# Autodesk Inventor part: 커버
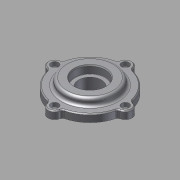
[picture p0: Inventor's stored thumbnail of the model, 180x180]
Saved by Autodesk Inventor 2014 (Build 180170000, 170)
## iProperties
Company: 한국ATC센터
Created: 2015-12
Part Number: 커버
Document SubType Name: Modeling
Designer: mdu
Density: 1 g/cm^3
Material: 일반
Mass: 49.9043 g
Surface Area: 145.431 cm^2
Volume: 49.9043 cm^3
Appearance: Default
Author: mdu
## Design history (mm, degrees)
sketch "스케치1"
  geometry: C1 r 1.621 at (0, 6.75) reference; C2 r 1.621 at (-37, -30.25) reference; C3 r 1.621 at (0, -67.25) reference; C4 r 1.621 at (37, -30.25) reference; C5 r 10 at (0, -30.25) reference; C6 r 12 at (0, -30.25); C7 r 24.5 at (0, -30.25) reference; A1 r 3 centre (-38.77, -20.408) between (-38.239, -23.361) and (-35.862, -21.146) reference; A2 r 7 centre (-37, -30.25) between (-38.239, -23.361) and (-38.239, -37.139) reference; A3 r 3 centre (-38.77, -40.092) between (-35.862, -39.354) and (-38.239, -37.139) reference; A4 r 37 centre (0, -30.25) between (-35.862, -39.354) and (-9.104, -66.113) reference; A5 r 3 centre (-9.842, -69.02) between (-6.889, -68.489) and (-9.104, -66.113) reference; A6 r 7 centre (0, -67.25) between (-6.889, -68.489) and (6.889, -68.489) reference; A7 r 3 centre (9.842, -69.02) between (9.104, -66.112) and (6.889, -68.489) reference; A8 r 37 centre (0, -30.25) between (9.104, -66.112) and (35.863, -39.354) reference; A9 r 3 centre (38.77, -40.092) between (38.239, -37.139) and (35.863, -39.354) reference; A10 r 7 centre (37, -30.25) between (38.239, -37.139) and (38.239, -23.361) reference; A11 r 3 centre (38.77, -20.408) between (35.863, -21.146) and (38.239, -23.361) reference; A12 r 37 centre (0, -30.25) between (35.863, -21.146) and (9.104, 5.612) reference; A13 r 3 centre (9.842, 8.52) between (6.889, 7.989) and (9.104, 5.612) reference; A14 r 7 centre (0, 6.75) between (6.889, 7.989) and (-6.889, 7.989) reference; A15 r 3 centre (-9.842, 8.52) between (-9.104, 5.612) and (-6.889, 7.989) reference; A16 r 37 centre (0, -30.25) between (-9.104, 5.612) and (-35.862, -21.146) reference; 1 further point
  constraints: 1 centre point, 1 coincident
  dimensions: "d2" = 2 radial gap between concentric circles of C6 C5
extrude "돌출1" new body sketch "스케치1" distance "d0" = 8; taper "d1" = 0 deg
sketch "스케치2"
  geometry: C1 r 23.5 at (0, -30.25) reference; C2 r 12 at (0, -30.25) reference; 1 further point
extrude "돌출2" join sketch "스케치2" distance "d4" = 5; taper "d5" = 0 deg
sketch "스케치3"
  geometry: C1 r 23.5 at (0, 0) reference; C2 r 20.5 at (0, 0); 1 further point
  constraints: 1 centre point
  dimensions: "d6" = 3 radial gap between concentric circles of C2 C1
node "작업 평면1"
extrude "돌출3" join sketch "스케치3" stored distance "d7" = 5; taper "d8" = 0 deg
fillet "모깎기1" dims "d9" = 3
sketch "스케치4"
  geometry: C1 r 12 at (0, -30.25) reference; C2 r 27 at (0, -30.25); 1 further point
  constraints: 1 centre point
  dimensions: "d10" = 15 radial gap between concentric circles of C1 C2
extrude "돌출4" join sketch "스케치4" distance "d11" = 7; taper "d12" = 0 deg
fillet "모깎기2" dims "d13" = 3
chamfer "모따기1" distance "d14" = 1; stored, may be unused: second distance "d15" = 2, angle "d16" = 45 deg
node "작업점1"
  node "작업축1"
chamfer "모따기2" distance "d24" = 1; stored, may be unused: second distance "d25" = 2, angle "d26" = 45 deg
hole "구멍6" diameter "d43" = 4.5; stored, may be unused: countersink angle "d47" = 90 deg, drill point angle "d49" = 118 deg; dims "d41" = 10, "d42" = 10, "d44" = 6, "d45" = 8, "d46" = 4.4, "d48" = 8
sketch "스케치8"
  geometry: C1 r 12 at (0, 0) reference; C2 r 16 at (0, 0); 1 further point
  constraints: 1 centre point, 1 coincident
  dimensions: "d53" = 32 diameter of C2
extrude "돌출5" cut sketch "스케치8" distance "d54" = 8.3; taper "d55" = 0 deg
fillet "모깎기3" dims "d56" = 0.3
chamfer "모따기3" distance "d57" = 1.2; stored, may be unused: second distance "d58" = 2, angle "d59" = 30 deg
node "솔리드1"
pattern_circular "원형 패턴1" dims angle "d51" = 360 deg
node "참조1"
node "참조2"
